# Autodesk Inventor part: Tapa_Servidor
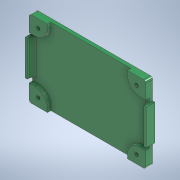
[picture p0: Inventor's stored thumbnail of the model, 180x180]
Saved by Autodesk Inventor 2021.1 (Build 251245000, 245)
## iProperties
Created: 2021-06
Part Number: Tapa_Servidor
Material: Genérico
Document SubType Name: Modeling
Designer: Ricardo
Density: 1 g/cm^3
Appearance: Valor por defecto
Author: Ricardo
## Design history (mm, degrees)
sketch "Boceto1"
  geometry: L1 (-51, -33.5)-(51, -33.5); L2 (51, -33.5)-(51, 33.5); L3 (51, 33.5)-(-51, 33.5); L4 (-51, 33.5)-(-51, -33.5); L5 (-51, -33.5)-(51, 33.5); L6 (51, -33.5)-(-51, 33.5); L7 (-43, -26.25)-(43, -26.25); L8 (43, -26.25)-(43, 26.25); L9 (43, 26.25)-(-43, 26.25); L10 (-43, 26.25)-(-43, -26.25); L11 (-43, -26.25)-(43, 26.25); L12 (43, -26.25)-(-43, 26.25); L13 (-35, 19)-(-51, 19); L14 (-51, 19)-(-51, 33.5); L15 (-51, 33.5)-(-35, 33.5); L16 (-35, 33.5)-(-35, 19); L17 (-35, 19)-(-51, 33.5); L18 (-51, 19)-(-35, 33.5); L19 (-35, -19)-(-51, -19); L20 (-51, -19)-(-51, -33.5); L21 (-51, -33.5)-(-35, -33.5); L22 (-35, -33.5)-(-35, -19); L23 (-35, -19)-(-51, -33.5); L24 (-51, -19)-(-35, -33.5); L25 (35, -19)-(51, -19); L26 (51, -19)-(51, -33.5); L27 (51, -33.5)-(35, -33.5); L28 (35, -33.5)-(35, -19); L29 (35, -19)-(51, -33.5); L30 (51, -19)-(35, -33.5); L31 (35, 19)-(51, 19); L32 (51, 19)-(51, 33.5); L33 (51, 33.5)-(35, 33.5); L34 (35, 33.5)-(35, 19); L35 (35, 19)-(51, 33.5); L36 (51, 19)-(35, 33.5); C1 r 1.5 at (43, 26.25); C2 r 1.5 at (-43, 26.25); C3 r 1.5 at (-43, -26.25); C4 r 1.5 at (43, -26.25); 10 further points
  constraints: 72 end point, 12 midpoint, 12 parallel, 6 horizontal, 6 perpendicular, 4 centre point, 4 coincident, 1 point on line
  dimensions: "d0" = 102 distance of L3.end L2.end; "d1" = 67 distance of L2.end L1.end; "d2" = 86 distance of L9.end L8.end; "d3" = 52.5 distance of L8.end L7.end; "d4" = 3 diameter of C1; "d5" = 3 diameter of C2; "d6" = 3 diameter of C3; "d7" = 3 diameter of C4
extrude "Extrusión1" new body sketch "Boceto1" distance "d8" = 3; taper "d9" = 0 deg
extrude "Extrusión2" join sketch "Boceto1" distance "d10" = 3; taper "d11" = 0 deg
fillet "Empalme1" dims "d12" = 11
sketch "Boceto2"
  geometry: L1 (-51, 33.5)-(-51, -33.5) reference; L2 (-51, -33.5)-(51, -33.5) reference; L3 (51, -33.5)-(51, 33.5) reference; L4 (51, 33.5)-(-51, 33.5) reference; C1 r 1.5 at (-43, 26.25) reference; C2 r 1.5 at (43, 26.25) reference; C3 r 1.5 at (43, -26.25) reference; C4 r 1.5 at (-43, -26.25) reference; C5 r 2.5 at (43, -26.25); C6 r 1.5 at (-43, -26.25) reference; C7 r 2.5 at (-43, -26.25); C8 r 1.5 at (-43, 26.25) reference; C9 r 2.5 at (-43, 26.25); C10 r 2.5 at (43, 26.25); 1 further point
  constraints: 4 centre point, 4 coincident
  dimensions: "d13" = 5 diameter of C5; "d14" = 5 diameter of C7; "d15" = 5 diameter of C9; "d16" = 5 diameter of C10
extrude "Extrusión3" cut sketch "Boceto2" distance "d17" = 2; taper "d18" = 0 deg
sketch "Boceto4"
  geometry: L1 (51, -33.5)-(51, 33.5) reference; L2 (51, 0)-(53, 0); L3 (51, 15.4)-(53, 15.4); L4 (53, 15.4)-(53, -15.4); L5 (53, -15.4)-(51, -15.4); L6 (51, -15.4)-(51, 15.4); L7 (51, 15.4)-(53, -15.4); L8 (53, 15.4)-(51, -15.4); 4 further points
  constraints: 14 end point, 4 midpoint, 3 parallel, 1 horizontal, 1 perpendicular
  dimensions: "d19" = 2 distance of L2.start L2.end; "d20" = 30.8 distance of L3.end L4.end
extrude "Extrusión4" join sketch "Boceto4" distance "d21" = 7.6; taper "d22" = 0 deg
mirror "Simetría1"
sketch "Boceto5" dims "d2" = 86
  geometry: L1 (-51, 33.5)-(51, 33.5); L2 (51, 33.5)-(51, -33.5); L3 (51, -33.5)-(-51, -33.5); L4 (-51, -33.5)-(-51, 33.5); 3 further points
  constraints: 2 coincident, 2 other
extrude "Extrusión5" cut sketch "Boceto5" distance "d23" = 2; taper "d24" = 0 deg
fillet "Empalme2" dims "d25" = 2
fillet "Empalme3" dims "d26" = 3
node "Sólido1"
node "Contorno proyectado1"
